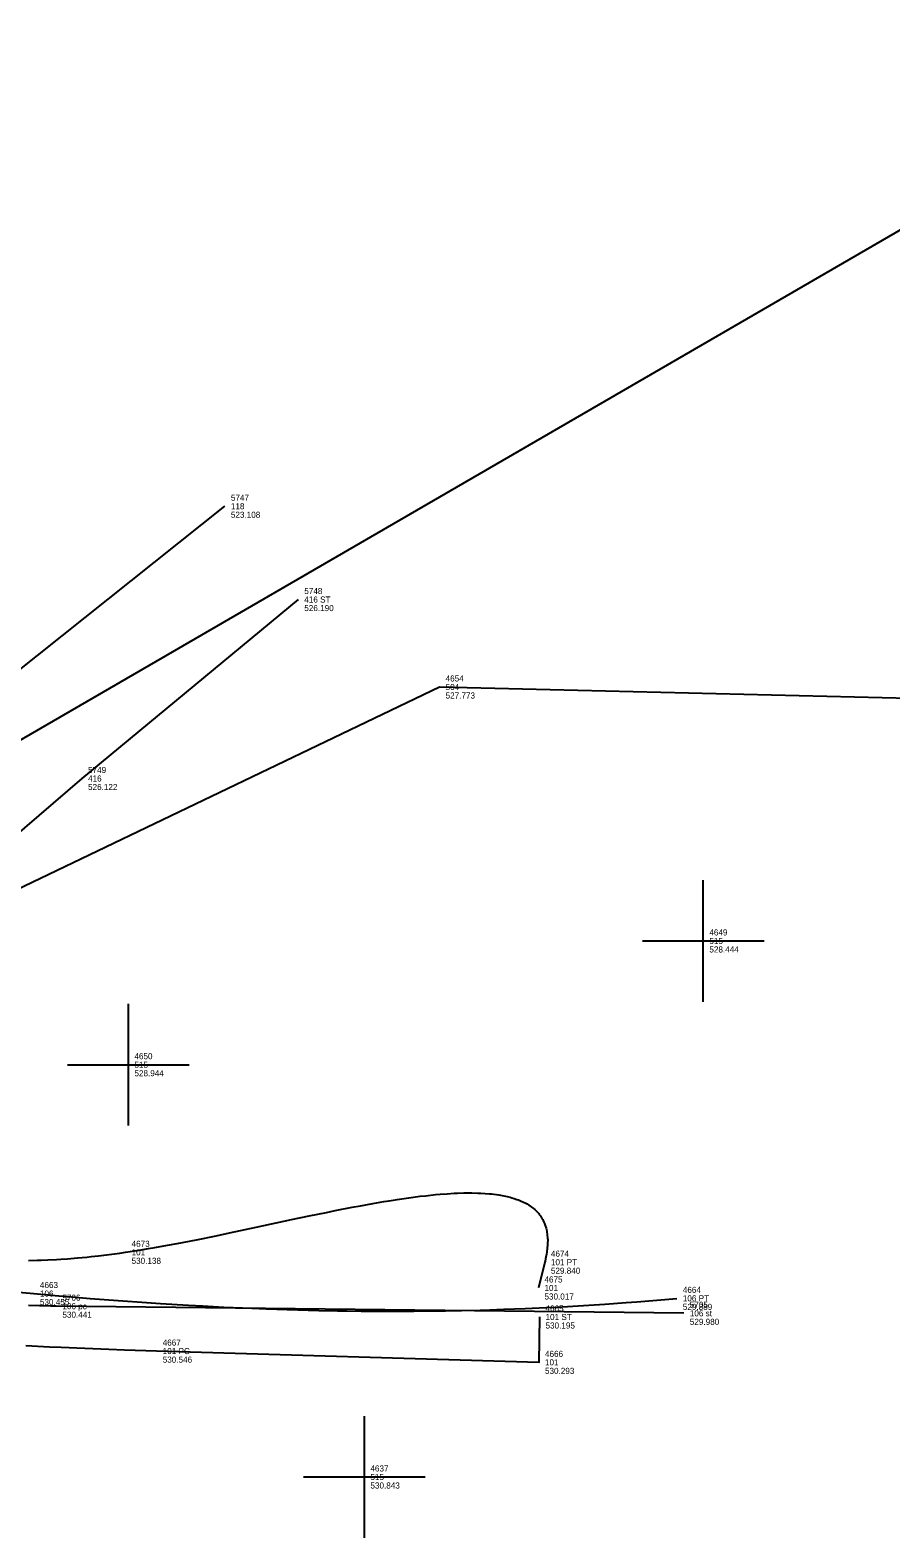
# Model space of a CAD drawing. Extents: x 5447 to 709667, y 4528 to 375505.
# Drawn here: x 705478.3 to 705513.7, y 375250 to 375311.9 of the extents above; entities that cross this region are included whole.
import ezdxf

# ---------------------------------------------------------------- set-up
doc = ezdxf.new("R2010")
doc.units = 0
for name, color, linetype in [('SV_DRAN_RIPRAP', 7, 'Continuous'), ('SV_GDRL_GR', 7, 'Continuous'), ('SV_NODES_ACTIVE_POINT', 7, 'Continuous'), ('SV_NODES_DESCRIPTION', 7, 'Continuous'), ('SV_NODES_ELEVATION', 7, 'Continuous'), ('SV_NODES_PT_NUMBER', 7, 'Continuous'), ('SV_ROAD_BITRD', 7, 'Continuous'), ('SV_SURF_SPOT', 7, 'Continuous'), ('SV_TREE_TREELN', 7, 'Continuous'), ('SV_WATR_INWETF', 7, 'Continuous'), ('SV_WATR_STREAM', 7, 'Continuous')]:
    doc.layers.add(name, color=color, linetype=linetype)

msp = doc.modelspace()

# ---------------------------------------------------------------- linework, layer by layer
at = {"layer": 'SV_DRAN_RIPRAP'}
msp.add_lwpolyline([(705489.353, 375288.542), (705480.464, 375281.19), (705472.788, 375274.596)], dxfattribs=at)
at = {"layer": 'SV_GDRL_GR'}
for points in [[(705477.55, 375260.12), (705478.486, 375260.03), (705479.515, 375259.937), (705480.03, 375259.893), (705480.801, 375259.829), (705481.958, 375259.739), (705483.114, 375259.658), (705483.692, 375259.62), (705484.849, 375259.55), (705485.427, 375259.518), (705486.294, 375259.474), (705487.45, 375259.423), (705488.029, 375259.401), (705488.896, 375259.372), (705489.764, 375259.348), (705490.198, 375259.337), (705490.97, 375259.323), (705491.356, 375259.317), (705491.935, 375259.31), (705492.803, 375259.304), (705493.672, 375259.304), (705494.107, 375259.306), (705494.977, 375259.314), (705495.412, 375259.321), (705496.065, 375259.333), (705496.839, 375259.351), (705497.226, 375259.362), (705497.807, 375259.381), (705498.679, 375259.414), (705499.552, 375259.453), (705499.988, 375259.475), (705500.862, 375259.524), (705501.299, 375259.55), (705501.955, 375259.593), (705502.83, 375259.656), (705503.268, 375259.69), (705503.926, 375259.744), (705504.913, 375259.832)], [(705505.202, 375259.218), (705479.41, 375259.51), (705479.18, 375259.513), (705478.873, 375259.519), (705478.72, 375259.523), (705478.261, 375259.536)]]:
    msp.add_lwpolyline(points, dxfattribs=at)
at = {"layer": 'SV_NODES_ACTIVE_POINT'}
for p, q in [((705486.336, 375292.375), (705486.336, 375292.375)), ((705489.353, 375288.542), (705489.353, 375288.542)), ((705495.162, 375284.95), (705495.162, 375284.95)), ((705480.464, 375281.19), (705480.464, 375281.19)), ((705482.254, 375261.725), (705482.254, 375261.725)), ((705499.49, 375261.319), (705499.49, 375261.319)), ((705478.486, 375260.03), (705478.486, 375260.03)), ((705499.225, 375260.258), (705499.225, 375260.258)), ((705479.41, 375259.51), (705479.41, 375259.51)), ((705504.913, 375259.832), (705504.913, 375259.832)), ((705499.269, 375259.067), (705499.269, 375259.067)), ((705505.202, 375259.218), (705505.202, 375259.218)), ((705483.533, 375257.666), (705483.533, 375257.666)), ((705499.247, 375257.203), (705499.247, 375257.203))]:
    msp.add_line(p, q, dxfattribs=at)
at = {"layer": 'SV_ROAD_BITRD'}
for points in [[(705478.272, 375261.391), (705478.617, 375261.398), (705478.791, 375261.404), (705479.055, 375261.414), (705479.411, 375261.432), (705479.592, 375261.442), (705479.865, 375261.461), (705480.281, 375261.494), (705480.658, 375261.529), (705480.849, 375261.548), (705481.137, 375261.579), (705481.578, 375261.632), (705482.026, 375261.692), (705482.254, 375261.725), (705482.817, 375261.811), (705483.199, 375261.874), (705483.456, 375261.919), (705483.976, 375262.012), (705484.371, 375262.086), (705485.17, 375262.242), (705485.98, 375262.407), (705486.525, 375262.52), (705487.618, 375262.753), (705489.075, 375263.065), (705489.797, 375263.217), (705490.513, 375263.364), (705490.867, 375263.435), (705491.567, 375263.572), (705491.913, 375263.637), (705492.424, 375263.729), (705492.87, 375263.806), (705493.091, 375263.842), (705493.417, 375263.893), (705493.898, 375263.963), (705494.366, 375264.024), (705494.596, 375264.05), (705494.995, 375264.092), (705495.19, 375264.109), (705495.478, 375264.131), (705495.758, 375264.148), (705495.895, 375264.154), (705496.165, 375264.162), (705496.296, 375264.164), (705496.49, 375264.165), (705496.742, 375264.159), (705496.864, 375264.155), (705497.044, 375264.144), (705497.219, 375264.13), (705497.304, 375264.121), (705497.598, 375264.083), (705497.738, 375264.059), (705497.874, 375264.032), (705497.941, 375264.017), (705498.07, 375263.985), (705498.133, 375263.968), (705498.226, 375263.94), (705498.345, 375263.9), (705498.402, 375263.878), (705498.487, 375263.844), (705498.608, 375263.79), (705498.711, 375263.737), (705498.76, 375263.71), (705498.832, 375263.666), (705498.934, 375263.597), (705499.029, 375263.523), (705499.075, 375263.483), (705499.151, 375263.411), (705499.187, 375263.373), (705499.238, 375263.314), (705499.262, 375263.283), (705499.294, 375263.242), (705499.309, 375263.221), (705499.331, 375263.189), (705499.359, 375263.145), (705499.373, 375263.123), (705499.402, 375263.071), (705499.42, 375263.036), (705499.444, 375262.989), (705499.455, 375262.964), (705499.478, 375262.909), (705499.51, 375262.823), (705499.542, 375262.716), (705499.555, 375262.661), (705499.573, 375262.577), (705499.593, 375262.445), (705499.604, 375262.306), (705499.607, 375262.235), (705499.606, 375262.087), (705499.602, 375262.011), (705499.593, 375261.894), (705499.573, 375261.731), (705499.56, 375261.648), (705499.536, 375261.519), (705499.522, 375261.453), (705499.501, 375261.364), (705499.49, 375261.319), (705499.225, 375260.258)], [(705499.269, 375259.067), (705499.247, 375257.203), (705483.533, 375257.666), (705482.218, 375257.707), (705481.563, 375257.73), (705480.585, 375257.766), (705479.612, 375257.807), (705479.127, 375257.829), (705478.16, 375257.878)]]:
    msp.add_lwpolyline(points, dxfattribs=at)
at = {"layer": 'SV_SURF_SPOT'}
for p, q in [((705506.004, 375272.015), (705506.004, 375277.017)), ((705503.503, 375274.516), (705508.505, 375274.516)), ((705506.004, 375274.516), (705506.004, 375274.516)), ((705482.371, 375266.93), (705482.371, 375271.932)), ((705479.87, 375269.431), (705484.872, 375269.431)), ((705482.371, 375269.431), (705482.371, 375269.431)), ((705492.071, 375249.993), (705492.071, 375254.995)), ((705489.57, 375252.494), (705494.572, 375252.494)), ((705492.071, 375252.494), (705492.071, 375252.494))]:
    msp.add_line(p, q, dxfattribs=at)
at = {"layer": 'SV_TREE_TREELN'}
msp.add_lwpolyline([(705474.058, 375274.855), (705495.162, 375284.95), (705524.723, 375284.239), (705558.01, 375282.679), (705583.345, 375279.879), (705602.913, 375276.221)], dxfattribs=at)
at = {"layer": 'SV_WATR_INWETF'}
msp.add_lwpolyline([(705578.39, 375331.311), (705524.349, 375309.659), (705459.867, 375272.301), (705446.731, 375296.722), (705543.238, 375349.235), (705597.77, 375381.862)], dxfattribs=at)
at = {"layer": 'SV_WATR_STREAM'}
msp.add_lwpolyline([(705465.513, 375275.644), (705476.737, 375284.738), (705486.336, 375292.375)], dxfattribs=at)

# ---------------------------------------------------------------- texts
at = {"layer": 'SV_NODES_DESCRIPTION'}
for s, p in [('118', (705486.586, 375292.25)), ('416 ST', (705489.603, 375288.417)), ('504', (705495.412, 375284.825)), ('416', (705480.714, 375281.065)), ('515', (705506.254, 375274.391)), ('515', (705482.621, 375269.306)), ('101', (705482.504, 375261.6)), ('101 PT', (705499.74, 375261.194)), ('106', (705478.736, 375259.905)), ('101', (705499.475, 375260.133)), ('106 pc', (705479.66, 375259.385)), ('106 PT', (705505.163, 375259.707)), ('101 ST', (705499.519, 375258.942)), ('106 st', (705505.451, 375259.093)), ('101 PC', (705483.783, 375257.541)), ('101', (705499.497, 375257.078)), ('515', (705492.321, 375252.369))]:
    msp.add_text(s, height=0.25, dxfattribs=at).set_placement(p)
at = {"layer": 'SV_NODES_ELEVATION'}
for s, p in [('523.108', (705486.586, 375291.9)), ('526.190', (705489.603, 375288.067)), ('527.773', (705495.412, 375284.475)), ('526.122', (705480.714, 375280.715)), ('528.444', (705506.254, 375274.041)), ('528.944', (705482.621, 375268.956)), ('530.138', (705482.504, 375261.25)), ('529.840', (705499.74, 375260.844)), ('530.017', (705499.475, 375259.783)), ('530.455', (705478.736, 375259.555)), ('529.889', (705505.163, 375259.357)), ('530.441', (705479.66, 375259.035)), ('530.195', (705499.519, 375258.592)), ('529.980', (705505.451, 375258.743)), ('530.546', (705483.783, 375257.191)), ('530.293', (705499.497, 375256.728)), ('530.843', (705492.321, 375252.019))]:
    msp.add_text(s, height=0.25, dxfattribs=at).set_placement(p)
at = {"layer": 'SV_NODES_PT_NUMBER'}
for s, p in [('5747', (705486.586, 375292.6)), ('5748', (705489.603, 375288.767)), ('4654', (705495.412, 375285.175)), ('5749', (705480.714, 375281.415)), ('4649', (705506.254, 375274.741)), ('4650', (705482.621, 375269.656)), ('4673', (705482.504, 375261.95)), ('4674', (705499.74, 375261.544)), ('4675', (705499.475, 375260.483)), ('4663', (705478.736, 375260.255)), ('4664', (705505.163, 375260.057)), ('5706', (705479.66, 375259.735)), ('4665', (705499.519, 375259.292)), ('5705', (705505.451, 375259.443)), ('4667', (705483.783, 375257.891)), ('4666', (705499.497, 375257.428)), ('4637', (705492.321, 375252.719))]:
    msp.add_text(s, height=0.25, dxfattribs=at).set_placement(p)

doc.saveas('drawing.dxf')
